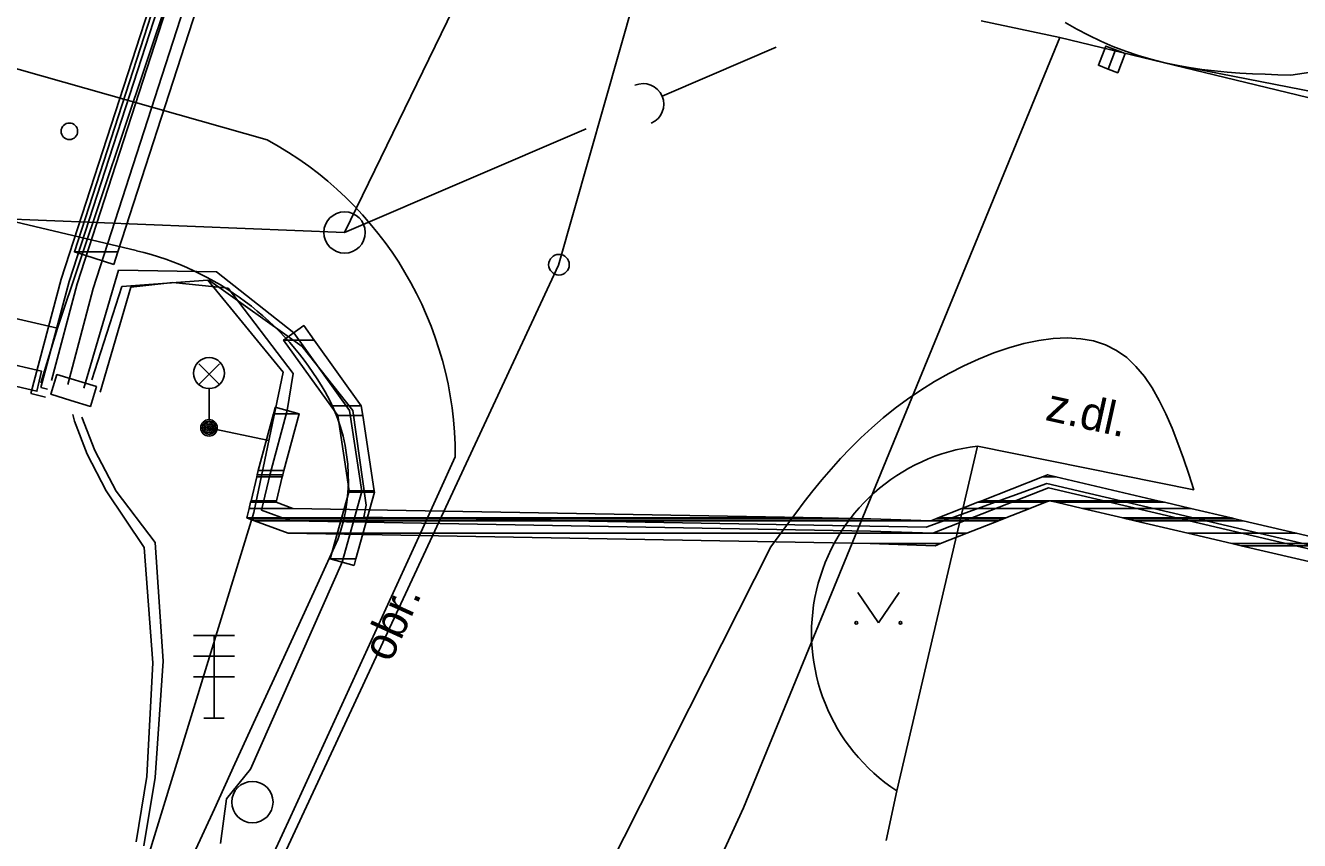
# Model space of a CAD drawing. Extents: x -614582 to -612559, y -1157748 to -1156203.
# Drawn here: x -613401.72 to -613370.89, y -1156900.96 to -1156881.22 of the extents above; entities that cross this region are included whole.
import ezdxf

# ---------------------------------------------------------------- set-up
doc = ezdxf.new("R2010")
doc.units = 0
for name, color, linetype in [('Vrstva 10', 7, 'Continuous'), ('Vrstva 11', 7, 'Continuous'), ('Vrstva 13', 7, 'Continuous'), ('Vrstva 14', 7, 'Continuous'), ('Vrstva 17', 7, 'Continuous'), ('Vrstva 20', 7, 'Continuous'), ('Vrstva 21', 7, 'Continuous'), ('Vrstva 34', 7, 'Continuous'), ('Vrstva 36', 7, 'Continuous'), ('Vrstva 4', 7, 'Continuous'), ('Vrstva 48', 7, 'Continuous'), ('Vrstva 51', 7, 'Continuous'), ('Vrstva 7', 7, 'Continuous')]:
    doc.layers.add(name, color=color, linetype=linetype)

# ---------------------------------------------------------------- blocks, each defined once
blk = doc.blocks.new('SC3401')
at = {"layer": 'Vrstva 10'}
blk.add_circle((0, 0), 2.5, dxfattribs=at)
blk = doc.blocks.new('SC3400')
at = {"layer": 'Vrstva 10'}
blk.add_circle((0, 0), 5, dxfattribs=at)
blk = doc.blocks.new('SC3419')
at = {"layer": 'Vrstva 14'}
for points in [[(0, 10), (-5, 10)], [(0, -10), (0, 10), (5, 10)], [(0, 5), (-5, 5)], [(0, 5), (5, 5)], [(0, 0), (-5, 0)], [(0, 0), (5, 0)], [(0, -10), (-2.5, -10)], [(0, -10), (2.5, -10)]]:
    blk.add_lwpolyline(points, dxfattribs=at)
blk = doc.blocks.new('SC3408')
at = {"layer": 'Vrstva 11'}
for points in [[(0, 5.5), (-2.5, 8)], [(0, 5.5), (2.5, 8)], [(0, 5.5), (-2.5, 3)], [(0, 5.5), (2.5, 3)], [(0, -5.5), (0, 2)]]:
    blk.add_lwpolyline(points, dxfattribs=at)
for centre, radius in [((0, 5.75), 3.75), ((0, -7.5), 2), ((0, -7.5), 1.6), ((0, -7.5), 1.2), ((0, -7.5), 0.8), ((0, -7.5), 0.4)]:
    blk.add_circle(centre, radius, dxfattribs=at)
blk = doc.blocks.new('SC3406')
at = {"layer": 'Vrstva 11'}
blk.add_lwpolyline([(0, -2.5), (5, -2.5), (5, 2.5), (-5, 2.5), (-5, -2.5), (0, -2.5)], dxfattribs=at)
blk = doc.blocks.new('SC3403')
at = {"layer": 'Vrstva 10'}
blk.add_lwpolyline([(2.5, 0), (2.5, 2.5), (-2.5, 2.5), (-2.5, 0), (2.5, 0), (2.5, -2.5), (-2.5, -2.5), (-2.5, 0)], dxfattribs=at)
blk = doc.blocks.new('SC3420')
at = {"layer": 'Vrstva 48'}
for points in [[(0, 0), (-12.5, 0)], [(0, 0), (17.5, 0)]]:
    blk.add_lwpolyline(points, dxfattribs=at)
blk.add_arc((-17.5, 0), 5, 270, 90, dxfattribs=at)

msp = doc.modelspace()

# ---------------------------------------------------------------- linework, layer by layer
at = {"layer": 'Vrstva 17'}
for p, q in [((-613378.591, -1156881.116), (-613376.691, -1156881.516)), ((-613376.691, -1156881.516), (-613380.641, -1156891.146)), ((-613360.411, -1156885.466), (-613376.691, -1156881.516)), ((-613380.641, -1156891.146), (-613384.341, -1156900.166)), ((-613384.341, -1156900.166), (-613385.541, -1156902.746))]:
    msp.add_line(p, q, dxfattribs=at)
at = {"layer": 'Vrstva 20'}
for p, q in [((-613382.664, -1156865.331), (-613388.824, -1156887.027)), ((-613382.664, -1156865.331), (-613388.824, -1156887.027)), ((-613382.664, -1156865.331), (-613388.824, -1156887.027)), ((-613382.664, -1156865.331), (-613388.824, -1156887.027)), ((-613388.824, -1156887.027), (-613400.368, -1156911.818)), ((-613388.824, -1156887.027), (-613400.368, -1156911.818)), ((-613388.824, -1156887.027), (-613400.368, -1156911.818)), ((-613388.824, -1156887.027), (-613400.368, -1156911.818))]:
    msp.add_line(p, q, dxfattribs=at)
at = {"layer": 'Vrstva 34'}
for p, q in [((-613400.857, -1156887.366), (-613396.939, -1156875.257)), ((-613396.743, -1156875.3), (-613400.665, -1156887.422)), ((-613400.473, -1156887.479), (-613396.547, -1156875.343)), ((-613396.155, -1156875.429), (-613400.089, -1156887.593)), ((-613400.309, -1156890.008), (-613399.474, -1156887.152)), ((-613399.474, -1156887.152), (-613397.101, -1156887.186)), ((-613397.101, -1156887.186), (-613395.231, -1156888.666)), ((-613401.595, -1156890.131), (-613400.857, -1156887.366)), ((-613400.665, -1156887.422), (-613401.349, -1156889.988)), ((-613401.097, -1156889.821), (-613400.473, -1156887.479)), ((-613399.176, -1156887.559), (-613398.161, -1156887.446)), ((-613398.161, -1156887.446), (-613396.821, -1156887.586)), ((-613400.089, -1156887.593), (-613400.699, -1156889.916)), ((-613399.919, -1156890.1), (-613399.176, -1156887.559)), ((-613396.821, -1156887.586), (-613395.241, -1156889.646)), ((-613395.231, -1156888.666), (-613393.881, -1156890.546)), ((-613395.241, -1156889.646), (-613395.391, -1156890.546)), ((-613401.237, -1156890.227), (-613401.595, -1156890.131)), ((-613401.349, -1156889.988), (-613401.189, -1156890.031)), ((-613395.391, -1156890.546), (-613395.801, -1156892.076)), ((-613393.881, -1156890.546), (-613393.581, -1156892.506)), ((-613400.541, -1156890.803), (-613400.581, -1156890.64)), ((-613400.23, -1156891.602), (-613400.541, -1156890.803)), ((-613400.358, -1156890.709), (-613400.048, -1156891.518)), ((-613399.769, -1156892.49), (-613400.23, -1156891.602)), ((-613400.048, -1156891.518), (-613399.528, -1156892.498)), ((-613395.801, -1156892.076), (-613396.011, -1156892.956)), ((-613379.761, -1156893.516), (-613376.961, -1156892.416)), ((-613376.961, -1156892.416), (-613367.761, -1156894.576)), ((-613398.853, -1156893.86), (-613399.769, -1156892.49)), ((-613399.528, -1156892.498), (-613398.588, -1156893.738)), ((-613393.581, -1156892.506), (-613394.061, -1156894.216)), ((-613396.011, -1156892.956), (-613395.311, -1156893.216)), ((-613395.311, -1156893.216), (-613381.271, -1156893.466)), ((-613381.271, -1156893.466), (-613379.761, -1156893.516)), ((-613398.638, -1156896.658), (-613398.853, -1156893.86)), ((-613398.588, -1156893.738), (-613398.393, -1156896.614)), ((-613394.061, -1156894.216), (-613396.281, -1156899.226)), ((-613398.783, -1156899.407), (-613398.638, -1156896.658)), ((-613398.393, -1156896.614), (-613398.583, -1156899.429)), ((-613396.281, -1156899.226), (-613396.861, -1156899.946)), ((-613399.045, -1156900.99), (-613398.783, -1156899.407)), ((-613398.583, -1156899.429), (-613398.862, -1156901.088)), ((-613396.861, -1156899.946), (-613397.001, -1156901.026))]:
    msp.add_line(p, q, dxfattribs=at)
at = {"layer": 'Vrstva 36'}
for points in [[(-613400.538, -1156886.705), (-613399.486, -1156886.705), (-613395.86, -1156875.494), (-613396.912, -1156875.494)], [(-613399.586, -1156887.013), (-613399.586, -1156887.013), (-613399.486, -1156886.705), (-613400.538, -1156886.705)], [(-613395.475, -1156888.841), (-613394.736, -1156888.841), (-613394.987, -1156888.491), (-613394.987, -1156888.491)], [(-613394.335, -1156890.429), (-613393.595, -1156890.429), (-613394.736, -1156888.841), (-613395.475, -1156888.841)], [(-613395.723, -1156890.624), (-613395.101, -1156890.624), (-613395.681, -1156890.468)], [(-613394.167, -1156890.663), (-613393.559, -1156890.663), (-613393.595, -1156890.429), (-613394.335, -1156890.429)], [(-613396.092, -1156892.002), (-613395.47, -1156892.002), (-613395.101, -1156890.624), (-613395.723, -1156890.624)], [(-613393.887, -1156892.487), (-613393.281, -1156892.487), (-613393.559, -1156890.663), (-613394.167, -1156890.663)], [(-613396.127, -1156892.15), (-613395.51, -1156892.15), (-613395.497, -1156892.103), (-613396.116, -1156892.103)], [(-613396.116, -1156892.103), (-613395.497, -1156892.103), (-613395.47, -1156892.002), (-613396.092, -1156892.002)], [(-613377.104, -1156892.15), (-613376.784, -1156892.15), (-613376.984, -1156892.103)], [(-613396.265, -1156892.729), (-613395.649, -1156892.729), (-613395.51, -1156892.15), (-613396.127, -1156892.15)], [(-613378.578, -1156892.729), (-613374.317, -1156892.729), (-613376.784, -1156892.15), (-613377.104, -1156892.15)], [(-613396.274, -1156892.767), (-613395.658, -1156892.767), (-613395.649, -1156892.729), (-613396.265, -1156892.729)], [(-613394.35, -1156894.135), (-613393.726, -1156894.135), (-613393.275, -1156892.525), (-613393.898, -1156892.525)], [(-613393.898, -1156892.525), (-613393.275, -1156892.525), (-613393.281, -1156892.487), (-613393.887, -1156892.487)], [(-613378.675, -1156892.767), (-613377.035, -1156892.767), (-613376.938, -1156892.729), (-613378.578, -1156892.729)], [(-613376.776, -1156892.767), (-613374.155, -1156892.767), (-613374.317, -1156892.729), (-613376.938, -1156892.729)], [(-613396.364, -1156893.145), (-613382.443, -1156893.145), (-613395.255, -1156892.917), (-613396.31, -1156892.917)], [(-613396.31, -1156892.917), (-613395.255, -1156892.917), (-613395.658, -1156892.767), (-613396.274, -1156892.767)], [(-613379.637, -1156893.145), (-613377.996, -1156893.145), (-613377.416, -1156892.917), (-613379.057, -1156892.917)], [(-613379.057, -1156892.917), (-613377.416, -1156892.917), (-613377.035, -1156892.767), (-613378.675, -1156892.767)], [(-613376.137, -1156892.917), (-613373.516, -1156892.917), (-613374.155, -1156892.767), (-613376.776, -1156892.767)], [(-613375.167, -1156893.145), (-613372.545, -1156893.145), (-613373.516, -1156892.917), (-613376.137, -1156892.917)], [(-613396.307, -1156893.166), (-613381.263, -1156893.166), (-613382.443, -1156893.145), (-613396.364, -1156893.145)], [(-613396.178, -1156893.214), (-613379.813, -1156893.214), (-613381.263, -1156893.166), (-613396.307, -1156893.166)], [(-613395.367, -1156893.515), (-613378.938, -1156893.515), (-613378.172, -1156893.214), (-613396.178, -1156893.214)], [(-613379.813, -1156893.214), (-613378.172, -1156893.214), (-613378.05, -1156893.166), (-613379.691, -1156893.166)], [(-613379.691, -1156893.166), (-613378.05, -1156893.166), (-613377.996, -1156893.145), (-613379.637, -1156893.145)], [(-613375.077, -1156893.166), (-613372.455, -1156893.166), (-613372.545, -1156893.145), (-613375.167, -1156893.145)], [(-613374.873, -1156893.214), (-613372.251, -1156893.214), (-613372.455, -1156893.166), (-613375.077, -1156893.166)], [(-613373.591, -1156893.515), (-613370.968, -1156893.515), (-613372.251, -1156893.214), (-613374.873, -1156893.214)], [(-613381.279, -1156893.766), (-613379.577, -1156893.766), (-613378.938, -1156893.515), (-613395.367, -1156893.515)], [(-613372.522, -1156893.766), (-613369.899, -1156893.766), (-613370.968, -1156893.515), (-613373.591, -1156893.515)], [(-613379.709, -1156893.818), (-613379.709, -1156893.818), (-613379.577, -1156893.766), (-613381.279, -1156893.766)], [(-613372.301, -1156893.818), (-613369.677, -1156893.818), (-613369.899, -1156893.766), (-613372.522, -1156893.766)], [(-613370.317, -1156894.284), (-613367.692, -1156894.284), (-613369.677, -1156893.818), (-613372.301, -1156893.818)], [(-613393.772, -1156894.297), (-613393.772, -1156894.297), (-613393.726, -1156894.135), (-613394.35, -1156894.135)]]:
    msp.add_lwpolyline(points, close=True, dxfattribs=at)
at = {"layer": 'Vrstva 4'}
for p, q in [((-613371.101, -1156882.426), (-613363.691, -1156881.326)), ((-613404.071, -1156881.666), (-613395.871, -1156883.996)), ((-613374.111, -1156882.136), (-613345.041, -1156887.826)), ((-613409.901, -1156884.095), (-613399.041, -1156886.676)), ((-613378.681, -1156891.406), (-613380.631, -1156899.756)), ((-613373.441, -1156892.466), (-613378.681, -1156891.406)), ((-613389.651, -1156905.646), (-613383.681, -1156893.846)), ((-613380.631, -1156899.756), (-613380.891, -1156900.956))]:
    msp.add_line(p, q, dxfattribs=at)
for points in [[(-613376.557, -1156881.151), (-613376.279, -1156881.313), (-613375.993, -1156881.463), (-613375.7, -1156881.602), (-613375.403, -1156881.73), (-613375.1, -1156881.846), (-613374.795, -1156881.949), (-613374.487, -1156882.041), (-613374.179, -1156882.12), (-613373.87, -1156882.188), (-613373.562, -1156882.243), (-613373.254, -1156882.288), (-613372.946, -1156882.325), (-613372.638, -1156882.353), (-613372.33, -1156882.376), (-613372.023, -1156882.393), (-613371.716, -1156882.406), (-613371.408, -1156882.417), (-613371.101, -1156882.426)], [(-613383.681, -1156893.846), (-613383.482, -1156893.573), (-613383.283, -1156893.301), (-613383.081, -1156893.03), (-613382.875, -1156892.76), (-613382.665, -1156892.493), (-613382.449, -1156892.228), (-613382.227, -1156891.966), (-613381.996, -1156891.708), (-613381.755, -1156891.455), (-613381.505, -1156891.206), (-613381.242, -1156890.962), (-613380.967, -1156890.724), (-613380.678, -1156890.493), (-613380.374, -1156890.268), (-613380.054, -1156890.051), (-613379.719, -1156889.843), (-613379.372, -1156889.647), (-613379.016, -1156889.465), (-613378.654, -1156889.3), (-613378.289, -1156889.153), (-613377.923, -1156889.028), (-613377.559, -1156888.927), (-613377.2, -1156888.852), (-613376.85, -1156888.805), (-613376.51, -1156888.79), (-613376.184, -1156888.809), (-613375.874, -1156888.863), (-613375.583, -1156888.956), (-613375.315, -1156889.09), (-613375.07, -1156889.265), (-613374.846, -1156889.477), (-613374.641, -1156889.724), (-613374.454, -1156890.001), (-613374.281, -1156890.304), (-613374.122, -1156890.63), (-613373.973, -1156890.974), (-613373.832, -1156891.334), (-613373.698, -1156891.705), (-613373.569, -1156892.084), (-613373.441, -1156892.466)], [(-613391.321, -1156891.666), (-613392.117, -1156893.41), (-613392.913, -1156895.154), (-613393.711, -1156896.898), (-613394.51, -1156898.641), (-613395.311, -1156900.384), (-613396.115, -1156902.127)], [(-613394.161, -1156893.666), (-613394.659, -1156894.753), (-613395.157, -1156895.84), (-613395.655, -1156896.927), (-613396.154, -1156898.014), (-613396.653, -1156899.1), (-613397.152, -1156900.186), (-613397.653, -1156901.272)]]:
    msp.add_lwpolyline(points, dxfattribs=at)
msp.add_circle((-613400.661, -1156883.786), 0.2, dxfattribs=at)
for centre, radius, start, end in [((-613400.025, -1156891.645), 8.704, 359.8614, 61.4932), ((-613400.7, -1156893.657), 7.175, 29.7513, 76.6294), ((-613398.181, -1156892.217), 4.273, 340.1743, 29.7513), ((-613378.137, -1156895.936), 4.562, 96.8436, 236.8666)]:
    msp.add_arc(centre, radius, start, end, dxfattribs=at)
at = {"layer": 'Vrstva 48'}
for p, q in [((-613389.471, -1156876.916), (-613394.001, -1156886.236)), ((-613394.001, -1156886.236), (-613388.152, -1156883.724)), ((-613405.164, -1156885.787), (-613394.001, -1156886.236))]:
    msp.add_line(p, q, dxfattribs=at)
at = {"layer": 'Vrstva 51'}
for p, q in [((-613400.946, -1156888.55), (-613395.98, -1156873.693)), ((-613400.946, -1156888.55), (-613395.98, -1156873.693)), ((-613428.921, -1156882.152), (-613400.946, -1156888.55)), ((-613428.921, -1156882.152), (-613400.946, -1156888.55)), ((-613399.389, -1156887.547), (-613397.314, -1156887.387)), ((-613399.389, -1156887.547), (-613397.314, -1156887.387)), ((-613397.314, -1156887.387), (-613395.49, -1156889.621)), ((-613397.314, -1156887.387), (-613395.49, -1156889.621)), ((-613397.295, -1156887.382), (-613395.027, -1156888.996)), ((-613397.295, -1156887.382), (-613395.027, -1156888.996)), ((-613400.119, -1156889.804), (-613399.389, -1156887.547)), ((-613400.119, -1156889.804), (-613399.389, -1156887.547)), ((-613400.946, -1156888.55), (-613401.355, -1156889.878)), ((-613400.946, -1156888.55), (-613401.355, -1156889.878)), ((-613395.027, -1156888.996), (-613393.799, -1156890.543)), ((-613395.027, -1156888.996), (-613393.799, -1156890.543)), ((-613395.49, -1156889.621), (-613396.196, -1156893.018)), ((-613395.49, -1156889.621), (-613396.196, -1156893.018)), ((-613393.799, -1156890.543), (-613393.479, -1156892.838)), ((-613393.799, -1156890.543), (-613393.479, -1156892.838)), ((-613397.291, -1156890.967), (-613395.833, -1156891.27)), ((-613397.291, -1156890.967), (-613395.833, -1156891.27)), ((-613379.923, -1156893.371), (-613377.002, -1156892.316)), ((-613379.923, -1156893.371), (-613377.002, -1156892.316)), ((-613377.002, -1156892.316), (-613353.633, -1156897.779)), ((-613377.002, -1156892.316), (-613353.633, -1156897.779)), ((-613396.196, -1156893.018), (-613399.19, -1156902.755)), ((-613396.196, -1156893.018), (-613399.19, -1156902.755)), ((-613393.479, -1156892.838), (-613393.533, -1156893.131)), ((-613393.479, -1156892.838), (-613393.533, -1156893.131)), ((-613393.533, -1156893.131), (-613379.923, -1156893.371)), ((-613393.533, -1156893.131), (-613379.923, -1156893.371))]:
    msp.add_line(p, q, dxfattribs=at)
at = {"layer": 'Vrstva 7'}
for points in [[(-613381.08, -1156895.684), (-613381.58, -1156894.951)], [(-613381.08, -1156895.684), (-613380.58, -1156894.951)]]:
    msp.add_lwpolyline(points, dxfattribs=at)
for centre in [(-613381.614, -1156895.684), (-613380.547, -1156895.684)]:
    msp.add_circle(centre, 0.0333, dxfattribs=at)

# ---------------------------------------------------------------- block references
at = {"layer": 'Vrstva 10', "xscale": 0.09999999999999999, "yscale": 0.09999999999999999, "rotation": 68.92695753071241}
msp.add_blockref('SC3403', (-613375.431, -1156882.046), dxfattribs=at)
at = {"layer": 'Vrstva 11', "xscale": 0.1, "yscale": 0.10000000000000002}
msp.add_blockref('SC3408', (-613397.281, -1156890.216), dxfattribs=at)
at = {"layer": 'Vrstva 11'}
for p, xscale, yscale, rotation in [((-613401.88, -1156889.723), 0.10000000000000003, 0.10000000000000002, -12.917292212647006), ((-613400.557, -1156890.061), 0.09999999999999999, 0.1, -17.032808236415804)]:
    msp.add_blockref('SC3406', p, dxfattribs=dict(at, xscale=xscale, yscale=yscale, rotation=rotation))
at = {"layer": 'Vrstva 14', "xscale": 0.1, "yscale": 0.10000000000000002}
msp.add_blockref('SC3419', (-613397.161, -1156896.996), dxfattribs=at)
at = {"layer": 'Vrstva 21', "xscale": 0.1, "yscale": 0.10000000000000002}
msp.add_blockref('SC3401', (-613388.811, -1156887.016), dxfattribs=at)
at = {"layer": 'Vrstva 48', "xscale": 0.1, "yscale": 0.09999999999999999, "rotation": 23.24553501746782}
msp.add_blockref('SC3420', (-613385.166, -1156882.441), dxfattribs=at)
at = {"layer": 'Vrstva 48', "xscale": 0.1, "yscale": 0.10000000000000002}
for p in [(-613394.001, -1156886.236), (-613396.231, -1156900.026)]:
    msp.add_blockref('SC3400', p, dxfattribs=at)

# ---------------------------------------------------------------- texts
at = {"layer": 'Vrstva 13'}
for s, rotation, p in [('z.dl.', 347.4791, (-613377.065, -1156890.772)), ('obr.', 65.5996, (-613392.887, -1156896.67))]:
    msp.add_text(s, height=0.8, rotation=rotation, dxfattribs=at).set_placement(p)

doc.saveas('drawing.dxf')
